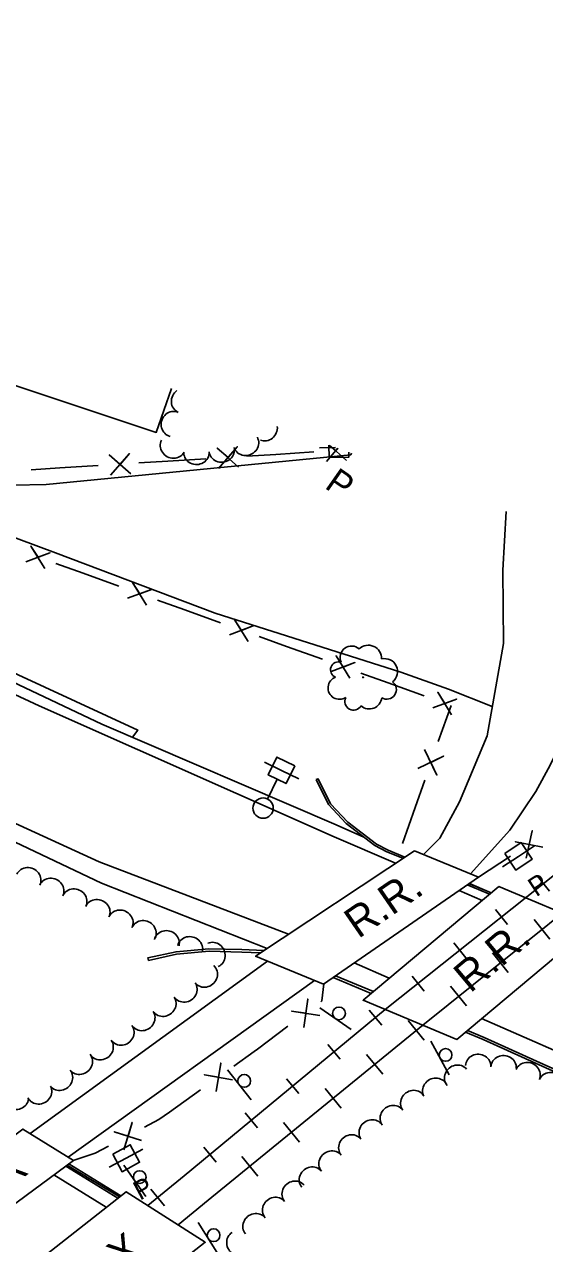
# Model space of a CAD drawing. Extents: x 1746010 to 1754829, y 655801 to 663091.
# Drawn here: x 1751859.2 to 1752063.6, y 659030.7 to 659509.7 of the extents above; entities that cross this region are included whole.
import ezdxf

# ---------------------------------------------------------------- set-up
doc = ezdxf.new("R2010")
doc.units = 0
for name, color, linetype in [('SURVEY - AERIAL SURVEY - Photo Control - Points - Elevations', 7, 'Continuous'), ('SURVEY - AERIAL SURVEY - Photo Control - Points - Locators', 7, 'Continuous'), ('SURVEY - AERIAL SURVEY - Photo Control - Points - Numbers', 7, 'Continuous'), ('SURVEY - AERIAL SURVEY - Photo Control with Text', 7, 'Continuous'), ('SURVEY - CENTERLINE - Existing Roads - Development', 7, 'Continuous'), ('SURVEY - CENTERLINE - Existing Roads Curve Text', 7, 'Continuous'), ('SURVEY - CENTERLINE - Existing Roads Text', 7, 'Continuous'), ('SURVEY - CONTROL - Points - Numbers', 7, 'Continuous')]:
    doc.layers.add(name, color=color, linetype=linetype)

msp = doc.modelspace()

# ---------------------------------------------------------------- linework, layer by layer
at = {"layer": 'SURVEY - AERIAL SURVEY - Photo Control - Points - Elevations'}
for points in [[(1751901.75, 659229.66), (1751903.78, 659232.49), (1751820.15, 659271.12), (1751720.09, 659319), (1751608.79, 659375.48), (1751511.86, 659425.67), (1751414.79, 659477.82), (1751309.42, 659535.79), (1751238.02, 659576.37), (1751119.98, 659647.33), (1751011.07, 659715.27), (1750920.63, 659773.68), (1750818.05, 659842.07), (1750688.97, 659930.51), (1750687.2, 659926.86)], [(1752012.39, 659185.07), (1751950.03, 659143.64), (1751976.68, 659132.64), (1752037.6, 659174.7)], [(1752037.6, 659174.7), (1752012.39, 659185.07)], [(1752045.59, 659171.03), (1751992.27, 659126.33), (1752029.04, 659110.92), (1752082.37, 659155.62)], [(1752082.37, 659155.62), (1752045.59, 659171.03)], [(1751808.51, 659038.41), (1751858.64, 659075.74), (1751878.49, 659063.36), (1751828.11, 659026.2)], [(1751849.79, 659012.16), (1751899.19, 659051.12), (1751930.3, 659031.24), (1751880.29, 658991.94)]]:
    msp.add_lwpolyline(points, dxfattribs=at)
at = {"layer": 'SURVEY - AERIAL SURVEY - Photo Control - Points - Locators'}
for p, q in [((1752065.45, 659169.2), (1752060.71, 659175.13)), ((1752049.04, 659156.09), (1752044.3, 659162.02)), ((1752059.42, 659158.11), (1752065.66, 659150.32)), ((1752032.63, 659142.98), (1752027.89, 659148.92)), ((1752043.03, 659144.98), (1752049.27, 659137.19)), ((1752016.23, 659129.88), (1752011.49, 659135.81)), ((1752026.64, 659131.85), (1752032.88, 659124.07)), ((1751999.56, 659116.6), (1751994.67, 659122.41)), ((1752009.99, 659118.32), (1752016.3, 659110.59)), ((1751983.31, 659103.15), (1751978.42, 659108.95)), ((1751993.65, 659104.98), (1751999.96, 659097.25)), ((1751967.05, 659089.69), (1751962.16, 659095.5)), ((1751977.31, 659091.63), (1751983.61, 659083.9)), ((1751950.8, 659076.23), (1751945.91, 659082.04)), ((1751960.96, 659078.29), (1751967.27, 659070.56)), ((1751934.55, 659062.78), (1751929.66, 659068.59)), ((1751944.62, 659064.94), (1751950.93, 659057.21)), ((1751908.92, 659052.11), (1751914.32, 659045.55))]:
    msp.add_line(p, q, dxfattribs=at)
for points in [[(1751980.95, 659190.5), (1751865.03, 659241.97), (1751755.82, 659292.86), (1751627.46, 659356.04), (1751498.69, 659424), (1751376.94, 659489.68), (1751250.14, 659561.52), (1751113.15, 659643.48), (1750975.97, 659727.83), (1750858.05, 659804.33), (1750722.4, 659896.24), (1750620.83, 659969.19)], [(1751981.66, 659195.26), (1751889.68, 659234.85), (1751784.21, 659284.64), (1751694.2, 659328.1), (1751603.81, 659373.71), (1751512.94, 659420.78), (1751440.06, 659459.77), (1751340.52, 659515.91), (1751224.32, 659581.45), (1751125.19, 659640.31), (1751025.2, 659702.76), (1750930.86, 659762.02), (1750841.47, 659821.93), (1750746.73, 659885.97), (1750687.69, 659926.53)], [(1751855.66, 659073.53), (1751824.49, 659092.89), (1751720.6, 659159.95), (1751578.18, 659253.97), (1751455.85, 659335.43), (1751347.45, 659406.77), (1751242.7, 659477.43), (1751134.7, 659551.49), (1751142.63, 659562.83), (1751231.24, 659513.59), (1751353.03, 659442.63), (1751480.52, 659374.44), (1751556.22, 659335.73), (1751679.55, 659272.32), (1751784.68, 659222.03), (1751889.47, 659172.35), (1751954.53, 659146.62)], [(1751917.01, 659366.66), (1751911.01, 659349.42), (1751799.61, 659386.46), (1751805.99, 659406.59)], [(1751987.66, 659341.25), (1751987.4, 659340.62), (1751867.82, 659328.98), (1751854.85, 659328.68), (1751847.65, 659330.71), (1751804.23, 659349.09), (1751755.74, 659377.39), (1751734.39, 659389.93)], [(1751727.73, 659378.09), (1751795.01, 659337.53), (1751841.46, 659313.28), (1751871.48, 659302.03), (1751934.15, 659278.45), (1752007.14, 659255.15), (1752025.75, 659248.5)], [(1752016.04, 659183.57), (1752022.45, 659189.99), (1752030.11, 659204.26), (1752041.01, 659230.22), (1752047.39, 659266.5), (1752047.1, 659295.34), (1752048.42, 659318.33)], [(1752136.1, 659280.15), (1752126.11, 659271.3), (1752110.04, 659287.75), (1752102.2, 659281.9), (1752091.24, 659269.92), (1752084.9, 659261.89), (1752081.32, 659254.58), (1752076.99, 659244.02), (1752071.76, 659231.08), (1752065.76, 659218.66), (1752060.06, 659208.3), (1752049.89, 659193.14), (1752034.39, 659176.02)], [(1751692.52, 659270.52), (1751888.55, 659180.68), (1751962.99, 659152.25)], [(1752175.58, 659262.96), (1752089.81, 659193.42), (1752000.96, 659122.69)], [(1752015.68, 659116.52), (1752114.5, 659195.85), (1752189.13, 659257.06)], [(1752025.75, 659248.5), (1752043.02, 659241.68)], [(1751981.66, 659195.26), (1751992.6, 659190.45)], [(1752005.01, 659180.16), (1751980.95, 659190.5)], [(1752039.04, 659165.53), (1752029.97, 659169.43)], [(1752034.05, 659172.25), (1752042.59, 659168.51)], [(1751861.5, 659073.96), (1751954.77, 659141.68)], [(1751988.76, 659140.98), (1752002.55, 659134.95)], [(1751973.17, 659134.09), (1751876.46, 659064.63)], [(1752000.96, 659122.69), (1751922.01, 659057.32)], [(1751931.43, 659047.73), (1752015.68, 659116.52)], [(1752038.8, 659119.1), (1752085.97, 659098.47), (1752111.93, 659087.93)], [(1751895.9, 659048.53), (1751875.54, 659061.18)], [(1751891.41, 659044.99), (1751870.8, 659057.69)], [(1751907.74, 659045.66), (1751922.01, 659057.32)], [(1751931.43, 659047.73), (1751919.63, 659038.06)]]:
    msp.add_lwpolyline(points, dxfattribs=at)
at = {"layer": 'SURVEY - AERIAL SURVEY - Photo Control - Points - Numbers'}
for points in [[(1751973.8, 659213.04), (1751974.62, 659213.29), (1751979.45, 659203.54), (1751986.24, 659196.23), (1751997.55, 659187.61), (1752002.09, 659185.24), (1752008.6, 659182.55)], [(1751973.8, 659213.04), (1751978.67, 659203.25), (1751985.57, 659195.81), (1751996.9, 659187.18), (1752001.57, 659184.68), (1752007.89, 659182.08)], [(1752033.16, 659171.64), (1752037.59, 659169.81), (1752041.94, 659167.96)], [(1752033.86, 659172.12), (1752037.87, 659170.47), (1752042.55, 659168.48)], [(1751953.3, 659145.81), (1751944.67, 659146.23), (1751931.72, 659146.57), (1751918.82, 659145.37), (1751907.7, 659142.93), (1751907.94, 659141.98)], [(1751951.94, 659144.9), (1751944.68, 659145.27), (1751931.78, 659145.6), (1751919, 659144.41), (1751907.94, 659141.98)], [(1751996.32, 659129.73), (1751981.41, 659135.9)], [(1751995.49, 659129.03), (1751980.46, 659135.25)], [(1752108.95, 659081.96), (1752104.6, 659083.62), (1752085.4, 659090.18), (1752064.05, 659099.73), (1752039.37, 659110.87), (1752032.42, 659113.75)], [(1752109.39, 659082.83), (1752104.92, 659084.53), (1752085.74, 659091.09), (1752064.47, 659100.61), (1752039.79, 659111.74), (1752033.25, 659114.45)], [(1751876.08, 659061.58), (1751896.56, 659049.05)], [(1751876.7, 659062.04), (1751897.16, 659049.52)]]:
    msp.add_lwpolyline(points, dxfattribs=at)
at = {"layer": 'SURVEY - AERIAL SURVEY - Photo Control with Text'}
for p, q in [((1751987.59, 659114.82), (1751975.28, 659123.38)), ((1752026.12, 659097.06), (1752018.93, 659110.23)), ((1751948.28, 659087.21), (1751939.03, 659099.02)), ((1751906.9, 659049.26), (1751898.26, 659061.52)), ((1751935.47, 659026.34), (1751927.53, 659039.06))]:
    msp.add_line(p, q, dxfattribs=at)
for centre in [(1751982.8, 659121.14), (1752024.66, 659104.86), (1751945.56, 659094.66), (1751904.56, 659056.84), (1751933.56, 659034.03)]:
    msp.add_circle(centre, 2.5, dxfattribs=at)
at = {"layer": 'SURVEY - CENTERLINE - Existing Roads - Development'}
for points in [[(1751935.47, 659335.26), (1751942.84, 659343.74), (1751939.21, 659339.5), (1751934.97, 659343.24), (1751943.34, 659335.75)], [(1751957.94, 659340.78), (1751972.89, 659341.72)], [(1751977.83, 659337.92), (1751982.38, 659343.15)], [(1751979.09, 659344.33), (1751985.71, 659338.42)], [(1751982.41, 659343.14), (1751981.57, 659342.16), (1751979.13, 659344.32)], [(1751893.1, 659332.6), (1751900.48, 659341.08), (1751896.84, 659336.84), (1751892.6, 659340.58), (1751900.98, 659333.09)], [(1751904.21, 659337.4), (1751915.57, 659338.12)], [(1751915.57, 659338.12), (1751930.53, 659339.06)], [(1751946.57, 659340.07), (1751957.94, 659340.78)], [(1751861.85, 659334.74), (1751873.21, 659335.46)], [(1751873.21, 659335.46), (1751888.16, 659336.4)], [(1751859.86, 659298.6), (1751869.24, 659302.1), (1751864.6, 659300.33), (1751861.82, 659304.77), (1751867.29, 659295.93)], [(1751871.58, 659297.91), (1751882.29, 659294.06)], [(1751882.29, 659294.06), (1751896.39, 659288.99)], [(1751899.8, 659284.23), (1751909.18, 659287.74), (1751904.54, 659285.97), (1751901.75, 659290.41), (1751907.23, 659281.56)], [(1751911.51, 659283.55), (1751922.23, 659279.69)], [(1751922.23, 659279.69), (1751936.32, 659274.62)], [(1751939.74, 659269.87), (1751949.11, 659273.38), (1751944.47, 659271.61), (1751941.69, 659276.05), (1751947.16, 659267.2)], [(1751951.45, 659269.18), (1751962.16, 659265.33)], [(1751962.16, 659265.33), (1751976.26, 659260.26)], [(1751979.67, 659255.51), (1751989.05, 659259.01), (1751984.41, 659257.24), (1751981.63, 659261.68), (1751987.1, 659252.84)], [(1751991.39, 659254.82), (1752002.1, 659250.97)], [(1752002.1, 659250.97), (1752016.19, 659245.9)], [(1752019.61, 659241.14), (1752028.99, 659244.65), (1752024.34, 659242.88), (1752021.56, 659247.32), (1752027.03, 659238.47)], [(1752026.79, 659242.08), (1752021.81, 659227.94)], [(1752016.43, 659224.84), (1752021.26, 659214.8), (1752018.83, 659219.77), (1752023.89, 659222.25), (1752013.8, 659217.39)], [(1752016.46, 659212.76), (1752012.67, 659202.02)], [(1752012.67, 659202.02), (1752007.69, 659187.87)], [(1752056.25, 659182.16), (1752058.69, 659192.9), (1752057.51, 659187.56), (1752052.06, 659188.59), (1752062.87, 659186.47)], [(1752037.6, 659174.7), (1752050.17, 659182.89)], [(1751975.66, 659125.75), (1751976.12, 659126.09), (1751976.88, 659132.78)], [(1751968.98, 659115.65), (1751970.53, 659126.78), (1751969.79, 659121.24), (1751964.2, 659122.05), (1751975.31, 659120.37)], [(1751950.74, 659107.14), (1751962.76, 659116.12)], [(1751941.48, 659100.49), (1751949.47, 659106.19), (1751950.74, 659107.14)], [(1751934.58, 659090.53), (1751936.37, 659101.63), (1751935.52, 659096.11), (1751929.94, 659097.04), (1751941.01, 659095.12)], [(1751916.17, 659082.42), (1751928.38, 659091.14)], [(1751898.27, 659067.58), (1751901.54, 659078.34), (1751899.95, 659072.98), (1751894.55, 659074.66), (1751905.26, 659071.26)], [(1751906.45, 659076.52), (1751912.03, 659079.46), (1751916.17, 659082.42)], [(1751878.42, 659063.31), (1751887.05, 659066.3), (1751892.21, 659069.02)]]:
    msp.add_lwpolyline(points, dxfattribs=at)
at = {"layer": 'SURVEY - CENTERLINE - Existing Roads Curve Text'}
for p, q in [((1751981.38, 659343.51), (1751975.19, 659343.37)), ((1751960.22, 659216.64), (1751953.48, 659219.92)), ((1751954.69, 659205.31), (1751958.51, 659213.13)), ((1751958.33, 659212.77), (1751956.93, 659209.89)), ((1751960.22, 659216.64), (1751966.96, 659213.34)), ((1752053.3, 659182.86), (1752059.55, 659187)), ((1752053.3, 659182.86), (1752047.04, 659178.71)), ((1751899.2, 659064.26), (1751892.58, 659060.72)), ((1751899.2, 659064.26), (1751905.81, 659067.81))]:
    msp.add_line(p, q, dxfattribs=at)
msp.add_lwpolyline([(1751986.63, 659341.62), (1751986.67, 659339.73), (1751978.88, 659339.55), (1751978.77, 659344.45)], dxfattribs=at)
for points in [[(1751965.44, 659218.43), (1751962.01, 659211.42), (1751955, 659214.84), (1751958.42, 659221.85)], [(1752047.89, 659183.95), (1752054.39, 659188.26), (1752058.7, 659181.76), (1752052.2, 659177.45)], [(1751893.92, 659065.85), (1751900.79, 659069.54), (1751904.48, 659062.67), (1751897.6, 659058.98)]]:
    msp.add_lwpolyline(points, close=True, dxfattribs=at)
msp.add_circle((1751952.98, 659201.8), 4, dxfattribs=at)
at = {"layer": 'SURVEY - CENTERLINE - Existing Roads Text'}
msp.add_circle((1751992.25, 659253.18), 0.158, dxfattribs=at)
for centre, radius, start, end in [((1751987.73, 659260.98), 4.51, 47.9365, 204.7255), ((1751994.35, 659260.67), 5.14, 356.9893, 134.5135), ((1752000.7, 659255.43), 5.11, 307.8851, 103.7236), ((1751982.57, 659256.17), 3.1, 70.0527, 248.7983), ((1751983, 659249.05), 4.5, 110.0734, 303.4931), ((1752001.58, 659248.38), 3.77, 238.138, 53.1383), ((1751988.53, 659243.73), 3.43, 152.6921, 330.0112), ((1751994.75, 659245.62), 4.86, 227.9791, 354.8248)]:
    msp.add_arc(centre, radius, start, end, dxfattribs=at)
for centre, major_axis, start_param, end_param in [((1751921.71, 659361.83), (2.06, 4.56), 1.009707, 3.141593), ((1751917.69, 659352.69), (1.2, 4.85), 0, 3.141593), ((1751953.84, 659351), (-1.91, -4.62), 0, 2.085185), ((1751917.55, 659344.01), (-4.41, 2.36), 0, 3.141593), ((1751946.33, 659345.1), (-4.4, -2.38), 0, 3.141593), ((1751926.85, 659341.49), (-5, -0.22), 0, 3.141593), ((1751936.78, 659342.38), (-4.88, -1.07), 0, 3.141593), ((1751860.81, 659173.69), (4.53, -2.11), 0, 3.141593), ((1751869.83, 659169.49), (4.53, -2.11), 0, 3.141593), ((1751878.86, 659165.3), (4.55, -2.08), 0, 3.141593), ((1751887.93, 659161.16), (4.55, -2.08), 0, 3.141593), ((1751896.99, 659157.01), (4.55, -2.08), 0, 3.141593), ((1751906.05, 659152.86), (4.55, -2.08), 0, 3.141593), ((1751915.13, 659148.96), (4.84, -1.24), 0, 3.141593), ((1751924.29, 659146.62), (4.84, -1.24), 0, 3.141593), ((1751933.35, 659144.14), (2.04, -4.57), 0, 3.141593), ((1751930.22, 659136.29), (-3.44, -3.63), 0, 3.141593), ((1751922.19, 659130.38), (-4.14, -2.8), 0, 3.141593), ((1751913.91, 659124.77), (-4.14, -2.8), 0, 3.141593), ((1751905.64, 659119.16), (-4.14, -2.8), 0, 3.141593), ((1751897.45, 659113.44), (-4.09, -2.87), 0, 3.141593), ((1751889.28, 659107.71), (-4.09, -2.87), 0, 3.141593), ((1751881.11, 659101.98), (-3.9, -3.13), 0, 3.141593), ((1752037.47, 659100.41), (4.99, -0.26), 0, 3.141593), ((1752047.45, 659099.9), (4.99, -0.26), 0, 3.141593), ((1752056.92, 659097.16), (4.6, -1.95), 0, 3.141593), ((1751873.33, 659095.74), (-3.9, -3.13), 0, 3.141593), ((1752029.1, 659096.07), (3.84, 3.2), 0, 3.141593), ((1752066.12, 659093.26), (4.6, -1.95), 0, 3.141593), ((1751865.08, 659090.31), (-4.46, -2.27), 0, 3.141593), ((1752020.57, 659090.99), (4.41, 2.36), 0, 3.141593), ((1751855.87, 659088.11), (-4.97, 0.57), 0, 3.141593), ((1752011.89, 659086.13), (4.03, 2.96), 0, 3.141593), ((1752003.83, 659080.21), (4.03, 2.96), 0, 3.141593), ((1751995.57, 659074.58), (4.14, 2.8), 0, 3.141593), ((1751987.52, 659068.67), (3.87, 3.16), 0, 3.141593), ((1751979.78, 659062.35), (3.87, 3.16), 0, 3.141593), ((1751972.03, 659056.02), (3.87, 3.16), 0, 3.141593), ((1751965.29, 659050.48), (3.85, 3.19), 0, 3.141593), ((1751957.59, 659044.1), (3.85, 3.19), 0, 3.141593), ((1751949.9, 659037.72), (3.85, 3.19), 0, 3.141593), ((1751943.46, 659030.89), (-2.65, 4.24), 0, 3.141593)]:
    msp.add_ellipse(centre, major_axis=major_axis, ratio=0.940188, start_param=start_param, end_param=end_param, dxfattribs=at)

# ---------------------------------------------------------------- texts
at = {"layer": 'SURVEY - CENTERLINE - Existing Roads Curve Text'}
for height, rotation, p in [(10, 325.02, (1751976.78, 659327.79)), (7.48, 33.5501, (1752060.27, 659166.73)), (7.48, 28.1996, (1751904.64, 659047.55))]:
    msp.add_text('P', height=height, rotation=rotation, dxfattribs=at).set_placement(p)
at = {"layer": 'SURVEY - CONTROL - Points - Numbers'}
for s, rotation, p in [('R.R.', 34.6248, (1751990.36, 659150.28)), ('R.R.', 39.9708, (1752034.32, 659128.89)), ('CSX', 36.4079, (1751834.64, 659038.76)), ('CSX', 38.1634, (1751880.37, 659005.99))]:
    msp.add_text(s, height=12, rotation=rotation, dxfattribs=at).set_placement(p)

doc.saveas('drawing.dxf')
